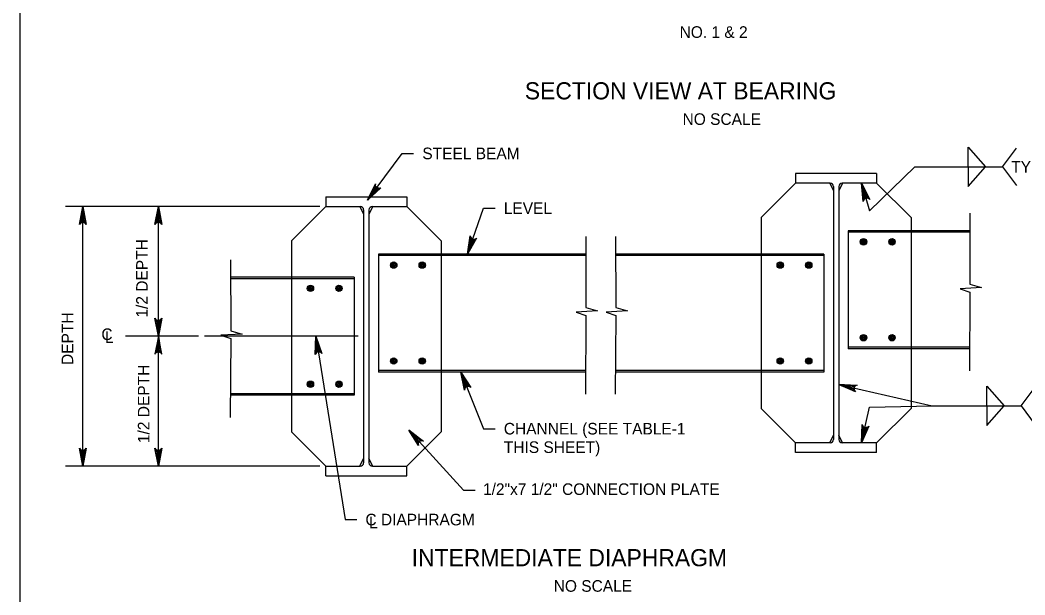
# Model space of a CAD drawing. Extents: x 638175 to 640495, y 294277 to 298435.
# Drawn here: x 639316.5 to 639576.6, y 296862.9 to 297011.5 of the extents above; entities that cross this region are included whole.
import ezdxf

# ---------------------------------------------------------------- set-up
doc = ezdxf.new("R2010")
doc.units = 0
for name, color, linetype in [('2', 7, 'Continuous'), ('3', 7, 'Continuous'), ('4', 7, 'Continuous'), ('5', 7, 'Continuous')]:
    doc.layers.add(name, color=color, linetype=linetype)

msp = doc.modelspace()

# ---------------------------------------------------------------- linework, layer by layer
at = {"layer": '2'}
msp.add_line((639316.46, 296668.46), (639316.46, 297232.46), dxfattribs=at)
for points in [[(639332.67, 296963.36), (639333.55, 296958.7), (639333.3, 296959.06), (639332.99, 296959.25), (639332.67, 296959.3), (639332.36, 296959.25), (639332.05, 296959.06), (639331.8, 296958.7), (639332.67, 296963.36), (639332.05, 296959.06), (639332.36, 296959.25), (639332.67, 296963.36), (639332.67, 296959.3), (639332.99, 296959.25), (639332.67, 296963.36), (639333.3, 296959.06)], [(639352.24, 296963.36), (639353.12, 296958.7), (639352.87, 296959.06), (639352.56, 296959.25), (639352.24, 296959.3), (639351.93, 296959.25), (639351.62, 296959.06), (639351.37, 296958.7), (639352.24, 296963.36), (639351.62, 296959.06), (639351.93, 296959.25), (639352.24, 296963.36), (639352.24, 296959.3), (639352.56, 296959.25), (639352.24, 296963.36), (639352.87, 296959.06)], [(639352.24, 296929.79), (639351.37, 296934.45), (639351.62, 296934.09), (639351.93, 296933.91), (639352.24, 296933.85), (639352.56, 296933.91), (639352.87, 296934.09), (639353.12, 296934.45), (639352.24, 296929.79), (639352.87, 296934.09), (639352.56, 296933.91), (639352.24, 296929.79), (639352.24, 296933.85), (639351.93, 296933.91), (639352.24, 296929.79), (639351.62, 296934.09)], [(639352.24, 296929.79), (639351.37, 296925.13), (639351.62, 296925.49), (639351.93, 296925.67), (639352.24, 296925.73), (639352.56, 296925.67), (639352.87, 296925.49), (639353.12, 296925.13), (639352.24, 296929.79), (639352.87, 296925.49), (639352.56, 296925.67), (639352.24, 296929.79), (639352.24, 296925.73), (639351.93, 296925.67), (639352.24, 296929.79), (639351.62, 296925.49)], [(639332.67, 296896.22), (639331.8, 296900.88), (639332.05, 296900.52), (639332.36, 296900.33), (639332.67, 296900.28), (639332.99, 296900.33), (639333.3, 296900.52), (639333.55, 296900.88), (639332.67, 296896.22), (639333.3, 296900.52), (639332.99, 296900.33), (639332.67, 296896.22), (639332.67, 296900.28), (639332.36, 296900.33), (639332.67, 296896.22), (639332.05, 296900.52)], [(639352.24, 296896.22), (639351.37, 296900.88), (639351.62, 296900.52), (639351.93, 296900.33), (639352.24, 296900.28), (639352.56, 296900.33), (639352.87, 296900.52), (639353.12, 296900.88), (639352.24, 296896.22), (639352.87, 296900.52), (639352.56, 296900.33), (639352.24, 296896.22), (639352.24, 296900.28), (639351.93, 296900.33), (639352.24, 296896.22), (639351.62, 296900.52)]]:
    msp.add_lwpolyline(points, dxfattribs=at)
at = {"layer": '3'}
for p, q in [((639561.86, 296978.71), (639566.39, 296973.62)), ((639561.86, 296973.62), (639561.86, 296978.71)), ((639406.35, 296964.98), (639415.33, 296977.08)), ((639415.33, 296977.08), (639418.33, 296977.08)), ((639570.77, 296973.62), (639574.34, 296978.46)), ((639536.32, 296962.22), (639548.07, 296973.62)), ((639548.07, 296973.62), (639570.77, 296973.62)), ((639561.86, 296968.54), (639566.39, 296973.62)), ((639561.86, 296973.62), (639561.86, 296968.54)), ((639570.77, 296973.62), (639574.34, 296968.78)), ((639534.24, 296969.38), (639536.32, 296962.22)), ((639394.04, 296963.36), (639328.17, 296963.36)), ((639332.67, 296896.22), (639332.67, 296963.36)), ((639352.24, 296929.79), (639352.24, 296963.36)), ((639432.27, 296951.06), (639436.42, 296962.91)), ((639436.42, 296962.91), (639439.42, 296962.91)), ((639562.26, 296961.61), (639562.32, 296943.25)), ((639462.87, 296955.59), (639462.93, 296937.24)), ((639470.58, 296955.59), (639470.64, 296937.24)), ((639370.91, 296949.58), (639370.97, 296931.22)), ((639565.33, 296942.37), (639559.81, 296942.07)), ((639562.32, 296943.25), (639565.33, 296942.37)), ((639559.81, 296942.07), (639562.32, 296941.21)), ((639562.32, 296941.21), (639562.2, 296920.85)), ((639462.93, 296937.24), (639465.94, 296936.36)), ((639470.64, 296937.24), (639473.65, 296936.36)), ((639465.94, 296936.36), (639460.42, 296936.05)), ((639460.42, 296936.05), (639462.93, 296935.19)), ((639462.93, 296935.19), (639462.81, 296914.83)), ((639473.65, 296936.36), (639468.13, 296936.05)), ((639468.13, 296936.05), (639470.64, 296935.19)), ((639470.64, 296935.19), (639470.52, 296914.83)), ((639362.61, 296929.79), (639343.77, 296929.79)), ((639352.24, 296896.22), (639352.24, 296929.79)), ((639373.98, 296930.34), (639368.45, 296930.04)), ((639368.45, 296930.04), (639370.97, 296929.18)), ((639370.97, 296929.18), (639370.84, 296908.82)), ((639370.97, 296931.22), (639373.98, 296930.34)), ((639393, 296929.79), (639400.6, 296882.4)), ((639430.54, 296920.55), (639436.42, 296905.9)), ((639528.38, 296917.3), (639552.56, 296911.77)), ((639566.69, 296916.86), (639571.23, 296911.77)), ((639566.69, 296911.77), (639566.69, 296916.86)), ((639575.61, 296911.77), (639579.18, 296916.61)), ((639534.24, 296902.23), (639536.32, 296911.43)), ((639536.32, 296911.43), (639552.56, 296911.77)), ((639552.56, 296911.77), (639575.61, 296911.77)), ((639566.69, 296911.77), (639566.69, 296906.69)), ((639566.69, 296906.69), (639571.23, 296911.77)), ((639575.61, 296911.77), (639579.18, 296906.93)), ((639436.42, 296905.9), (639439.42, 296905.9)), ((639417.06, 296905.55), (639431.23, 296890.01)), ((639394.04, 296896.22), (639328.17, 296896.22)), ((639431.23, 296890.01), (639434.23, 296890.01)), ((639400.6, 296882.4), (639403.6, 296882.4))]:
    msp.add_line(p, q, dxfattribs=at)
for points in [[(639406.35, 296964.98), (639408.43, 296969.25), (639408.41, 296968.81), (639408.55, 296968.47), (639408.77, 296968.25), (639409.05, 296968.1), (639409.41, 296968.06), (639409.83, 296968.2), (639406.35, 296964.98), (639409.41, 296968.06), (639409.05, 296968.1), (639406.35, 296964.98), (639408.77, 296968.25), (639408.55, 296968.47), (639406.35, 296964.98), (639408.41, 296968.81)], [(639534.24, 296969.38), (639536.38, 296965.14), (639536.04, 296965.42), (639535.69, 296965.51), (639535.37, 296965.47), (639535.09, 296965.34), (639534.84, 296965.07), (639534.7, 296964.66), (639534.24, 296969.38), (639534.84, 296965.07), (639535.09, 296965.34), (639534.24, 296969.38), (639535.37, 296965.47), (639535.69, 296965.51), (639534.24, 296969.38), (639536.04, 296965.42)], [(639432.27, 296951.06), (639432.99, 296955.75), (639433.1, 296955.33), (639433.34, 296955.05), (639433.61, 296954.9), (639433.93, 296954.84), (639434.28, 296954.91), (639434.64, 296955.17), (639432.27, 296951.06), (639434.28, 296954.91), (639433.93, 296954.84), (639432.27, 296951.06), (639433.61, 296954.9), (639433.34, 296955.05), (639432.27, 296951.06), (639433.1, 296955.33)], [(639393, 296929.79), (639394.6, 296925.33), (639394.3, 296925.64), (639393.96, 296925.77), (639393.64, 296925.78), (639393.34, 296925.67), (639393.07, 296925.44), (639392.88, 296925.05), (639393, 296929.79), (639393.07, 296925.44), (639393.34, 296925.67), (639393, 296929.79), (639393.64, 296925.78), (639393.96, 296925.77), (639393, 296929.79), (639394.3, 296925.64)], [(639430.54, 296920.55), (639433.09, 296916.55), (639432.73, 296916.79), (639432.37, 296916.84), (639432.06, 296916.78), (639431.79, 296916.61), (639431.57, 296916.32), (639431.47, 296915.9), (639430.54, 296920.55), (639431.57, 296916.32), (639431.79, 296916.61), (639430.54, 296920.55), (639432.06, 296916.78), (639432.37, 296916.84), (639430.54, 296920.55), (639432.73, 296916.79)], [(639528.38, 296917.3), (639533.12, 296917.11), (639532.72, 296916.95), (639532.47, 296916.69), (639532.34, 296916.39), (639532.33, 296916.08), (639532.44, 296915.73), (639532.73, 296915.41), (639528.38, 296917.3), (639532.44, 296915.73), (639532.33, 296916.08), (639528.38, 296917.3), (639532.34, 296916.39), (639532.47, 296916.69), (639528.38, 296917.3), (639532.72, 296916.95)], [(639534.24, 296902.23), (639534.41, 296906.97), (639534.58, 296906.56), (639534.84, 296906.31), (639535.13, 296906.19), (639535.45, 296906.18), (639535.8, 296906.29), (639536.12, 296906.58), (639534.24, 296902.23), (639535.8, 296906.29), (639535.45, 296906.18), (639534.24, 296902.23), (639535.13, 296906.19), (639534.84, 296906.31), (639534.24, 296902.23), (639534.58, 296906.56)], [(639417.06, 296905.55), (639420.85, 296902.7), (639420.42, 296902.79), (639420.07, 296902.72), (639419.8, 296902.55), (639419.6, 296902.3), (639419.5, 296901.95), (639419.56, 296901.52), (639417.06, 296905.55), (639419.5, 296901.95), (639419.6, 296902.3), (639417.06, 296905.55), (639419.8, 296902.55), (639420.07, 296902.72), (639417.06, 296905.55), (639420.42, 296902.79)]]:
    msp.add_lwpolyline(points, dxfattribs=at)
for points in [[(639534.6, 296966.36), (639535.56, 296966.63), (639534.24, 296969.38)], [(639408.54, 296967.09), (639407.74, 296967.69), (639406.35, 296964.98)], [(639332.17, 296960.36), (639333.17, 296960.36), (639332.67, 296963.36)], [(639351.74, 296960.36), (639352.74, 296960.36), (639352.24, 296963.36)], [(639433.73, 296953.73), (639432.79, 296954.06), (639432.27, 296951.06)], [(639351.74, 296932.79), (639352.74, 296932.79), (639352.24, 296929.79)], [(639351.74, 296926.79), (639352.74, 296926.79), (639352.24, 296929.79)], [(639392.98, 296926.75), (639393.97, 296926.91), (639393, 296929.79)], [(639431.2, 296917.58), (639432.12, 296917.95), (639430.54, 296920.55)], [(639531.2, 296916.14), (639531.42, 296917.12), (639528.38, 296917.3)], [(639418.71, 296903), (639419.45, 296903.67), (639417.06, 296905.55)], [(639535.39, 296905.05), (639534.41, 296905.27), (639534.24, 296902.23)], [(639332.17, 296899.22), (639333.17, 296899.22), (639332.67, 296896.22)], [(639351.74, 296899.22), (639352.74, 296899.22), (639352.24, 296896.22)]]:
    msp.add_lwpolyline(points, close=True, dxfattribs=at)
at = {"layer": '4'}
for p, q in [((639538.18, 296971.88), (639517.21, 296971.88)), ((639517.21, 296969.38), (639508.31, 296960.47)), ((639526.12, 296969.38), (639517.21, 296969.38)), ((639526.02, 296969.38), (639527.01, 296967.41)), ((639527.01, 296968.49), (639527.01, 296903.12)), ((639529.37, 296969.38), (639528.38, 296967.41)), ((639528.38, 296968.49), (639528.38, 296903.12)), ((639538.18, 296969.38), (639529.27, 296969.38)), ((639538.18, 296969.38), (639547.08, 296960.47)), ((639395.6, 296965.86), (639416.57, 296965.86)), ((639395.6, 296963.36), (639386.69, 296954.46)), ((639395.6, 296963.36), (639404.5, 296963.36)), ((639404.41, 296963.36), (639405.39, 296961.39)), ((639407.76, 296963.36), (639406.77, 296961.39)), ((639407.66, 296963.36), (639416.57, 296963.36)), ((639416.57, 296963.36), (639425.47, 296954.46)), ((639405.39, 296962.47), (639405.39, 296897.11)), ((639406.77, 296962.47), (639406.77, 296897.11)), ((639508.31, 296960.47), (639508.31, 296951.06)), ((639547.08, 296960.47), (639547.08, 296957.07)), ((639530.84, 296957.07), (639530.84, 296926.56)), ((639547.08, 296957.07), (639547.08, 296926.56)), ((639386.69, 296954.46), (639386.69, 296945.05)), ((639425.47, 296954.46), (639425.47, 296951.06)), ((639409.23, 296951.06), (639409.23, 296920.55)), ((639425.47, 296951.06), (639425.47, 296920.55)), ((639508.31, 296951.06), (639508.31, 296920.55)), ((639524.55, 296951.06), (639524.55, 296920.55)), ((639386.69, 296945.05), (639386.69, 296914.53)), ((639402.93, 296945.05), (639402.93, 296914.53)), ((639547.08, 296926.56), (639547.08, 296911.14)), ((639425.47, 296920.55), (639425.47, 296905.12)), ((639508.31, 296920.55), (639508.31, 296911.14)), ((639386.69, 296914.53), (639386.69, 296905.12)), ((639508.31, 296911.14), (639517.21, 296902.23)), ((639538.18, 296902.23), (639547.08, 296911.14)), ((639386.69, 296905.12), (639395.6, 296896.22)), ((639416.57, 296896.22), (639425.47, 296905.12)), ((639526.02, 296902.23), (639527.01, 296904.2)), ((639529.37, 296902.23), (639528.38, 296904.2)), ((639526.12, 296902.23), (639517.21, 296902.23)), ((639538.18, 296902.23), (639529.27, 296902.23)), ((639404.41, 296896.22), (639405.39, 296898.18)), ((639407.76, 296896.22), (639406.77, 296898.18)), ((639538.18, 296899.73), (639517.21, 296899.73)), ((639395.6, 296896.22), (639404.5, 296896.22)), ((639407.66, 296896.22), (639416.57, 296896.22)), ((639395.6, 296893.72), (639416.57, 296893.72))]:
    msp.add_line(p, q, dxfattribs=at)
for centre, radius in [((639534.78, 296954.22), 0.833), ((639534.78, 296954.22), 0.625), ((639534.78, 296954.22), 0.417), ((639534.78, 296954.22), 0.208), ((639542.16, 296954.22), 0.833), ((639542.16, 296954.22), 0.625), ((639542.16, 296954.22), 0.417), ((639542.16, 296954.22), 0.208), ((639413.17, 296948.2), 0.833), ((639413.17, 296948.2), 0.625), ((639413.17, 296948.2), 0.417), ((639413.17, 296948.2), 0.208), ((639420.55, 296948.2), 0.833), ((639420.55, 296948.2), 0.625), ((639420.55, 296948.2), 0.417), ((639420.55, 296948.2), 0.208), ((639513.23, 296948.2), 0.833), ((639513.23, 296948.2), 0.625), ((639513.23, 296948.2), 0.417), ((639513.23, 296948.2), 0.208), ((639520.61, 296948.2), 0.833), ((639520.61, 296948.2), 0.625), ((639520.61, 296948.2), 0.417), ((639520.61, 296948.2), 0.208), ((639391.61, 296942.19), 0.833), ((639391.61, 296942.19), 0.625), ((639391.61, 296942.19), 0.417), ((639391.61, 296942.19), 0.208), ((639399, 296942.19), 0.833), ((639399, 296942.19), 0.625), ((639399, 296942.19), 0.417), ((639399, 296942.19), 0.208), ((639534.78, 296929.42), 0.833), ((639534.78, 296929.42), 0.625), ((639534.78, 296929.42), 0.417), ((639534.78, 296929.42), 0.208), ((639542.16, 296929.42), 0.833), ((639542.16, 296929.42), 0.625), ((639542.16, 296929.42), 0.417), ((639542.16, 296929.42), 0.208), ((639413.17, 296923.4), 0.833), ((639413.17, 296923.4), 0.625), ((639420.55, 296923.4), 0.833), ((639420.55, 296923.4), 0.625), ((639513.23, 296923.4), 0.833), ((639513.23, 296923.4), 0.625), ((639520.61, 296923.4), 0.833), ((639520.61, 296923.4), 0.625), ((639413.17, 296923.4), 0.417), ((639413.17, 296923.4), 0.208), ((639420.55, 296923.4), 0.417), ((639420.55, 296923.4), 0.208), ((639513.23, 296923.4), 0.417), ((639513.23, 296923.4), 0.208), ((639520.61, 296923.4), 0.417), ((639520.61, 296923.4), 0.208), ((639391.61, 296917.39), 0.833), ((639391.61, 296917.39), 0.625), ((639391.61, 296917.39), 0.417), ((639391.61, 296917.39), 0.208), ((639399, 296917.39), 0.833), ((639399, 296917.39), 0.625), ((639399, 296917.39), 0.417), ((639399, 296917.39), 0.208)]:
    msp.add_circle(centre, radius, dxfattribs=at)
for centre, start, end in [((639526.12, 296968.49), 0, 90), ((639529.27, 296968.49), 90, 180), ((639404.5, 296962.47), 0, 90), ((639407.66, 296962.47), 90, 180), ((639526.12, 296903.12), 270, 0), ((639529.27, 296903.12), 180, 270), ((639404.5, 296897.11), 270, 0), ((639407.66, 296897.11), 180, 270)]:
    msp.add_arc(centre, 0.889, start, end, dxfattribs=at)
at = {"layer": '5'}
for p, q in [((639517.21, 296971.88), (639517.21, 296969.38)), ((639538.18, 296971.88), (639538.18, 296969.38)), ((639395.6, 296965.86), (639395.6, 296963.36)), ((639416.57, 296965.86), (639416.57, 296963.36)), ((639562.28, 296957.07), (639530.84, 296957.07)), ((639562.28, 296956.68), (639530.84, 296956.68)), ((639462.88, 296951.06), (639409.23, 296951.06)), ((639462.89, 296950.67), (639409.23, 296950.67)), ((639524.55, 296951.06), (639470.6, 296951.06)), ((639524.55, 296950.67), (639470.6, 296950.67)), ((639402.93, 296945.05), (639370.92, 296945.05)), ((639402.93, 296944.65), (639370.92, 296944.65)), ((639403.97, 296929.79), (639364.18, 296929.79)), ((639562.24, 296926.96), (639530.84, 296926.96)), ((639562.23, 296926.56), (639530.84, 296926.56)), ((639462.84, 296920.94), (639409.23, 296920.94)), ((639462.84, 296920.55), (639409.23, 296920.55)), ((639524.55, 296920.94), (639470.56, 296920.94)), ((639524.55, 296920.55), (639470.56, 296920.55)), ((639402.93, 296914.93), (639370.88, 296914.93)), ((639402.93, 296914.53), (639370.88, 296914.53)), ((639517.21, 296899.73), (639517.21, 296902.23)), ((639538.18, 296899.73), (639538.18, 296902.23)), ((639395.6, 296893.72), (639395.6, 296896.22)), ((639416.57, 296893.72), (639416.57, 296896.22))]:
    msp.add_line(p, q, dxfattribs=at)

# ---------------------------------------------------------------- texts
at = {"layer": '3'}
for s, height, p in [('NO. 1 & 2', 3, (639487.17, 297006.96)), ('SECTION VIEW AT BEARING', 4.4292, (639447.11, 296991.05)), ('NO SCALE', 3, (639487.94, 296984.45)), ('STEEL BEAM', 3, (639420.58, 296975.58)), ('TYP.', 3, (639573.02, 296972.12)), ('LEVEL', 3, (639441.67, 296961.41)), ('C', 3, (639337.5, 296928.82)), ('L', 3, (639338.44, 296928.05)), ('CHANNEL (SEE TABLE-1', 3, (639441.67, 296904.4)), ('THIS SHEET)', 3, (639441.67, 296899.62)), ('1/2"x7 1/2" CONNECTION PLATE', 3, (639436.28, 296888.76)), ('C DIAPHRAGM', 3, (639405.85, 296880.9)), ('L', 3, (639406.79, 296880.13)), ('INTERMEDIATE DIAPHRAGM', 4.4292, (639417.83, 296870.33)), ('NO SCALE', 3, (639454.59, 296863.73))]:
    msp.add_text(s, height=height, dxfattribs=at).set_placement(p)
for s, p in [('1/2 DEPTH', (639349.5, 296934.62)), ('DEPTH', (639330.2, 296922.36)), ('1/2 DEPTH', (639349.94, 296902.17))]:
    msp.add_text(s, height=3, rotation=90, dxfattribs=at).set_placement(p)

doc.saveas('drawing.dxf')
